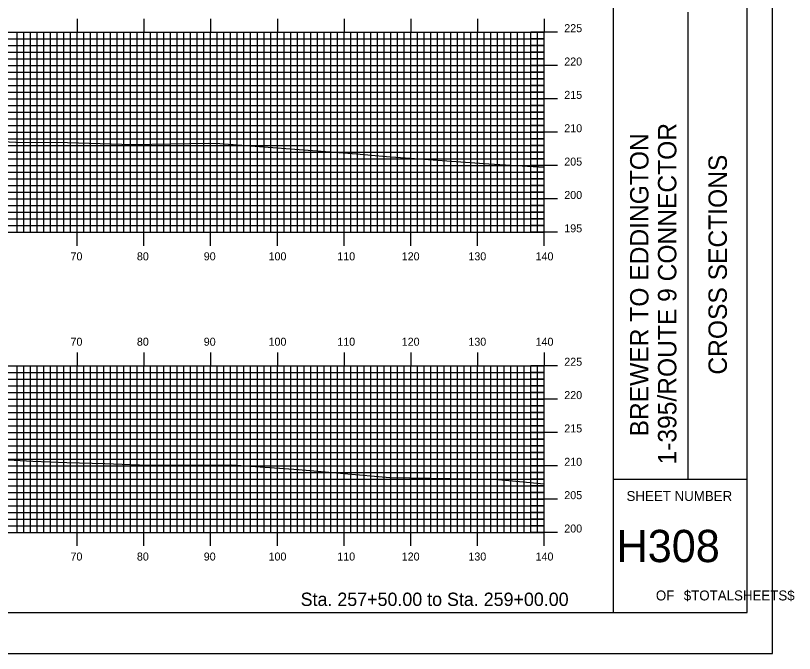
# Model space of a CAD drawing. Extents: x 1805471 to 1805814, y 442591 to 442811.
# Drawn here: x 1805697.5 to 1805814.2, y 442590.5 to 442686.2 of the extents above; entities that cross this region are included whole.
import ezdxf

# ---------------------------------------------------------------- set-up
doc = ezdxf.new("R2010")
doc.units = 0
for name, color, linetype in [('BORDER', 7, 'Continuous'), ('H_V ANNOTATION', 7, 'Continuous'), ('MAJOR', 7, 'Continuous'), ('MINOR', 7, 'Continuous'), ('PLOT BOUNDARY', 7, 'Continuous'), ('S_Roadway_Centerline', 7, 'Continuous')]:
    doc.layers.add(name, color=color, linetype=linetype)

msp = doc.modelspace()

# ---------------------------------------------------------------- linework, layer by layer
at = {"layer": 'BORDER'}
for p, q in [((1805787.11, 442596.67), (1805787.11, 442806.67)), ((1805798.29, 442616.67), (1805798.29, 442686.67)), ((1805787.11, 442616.67), (1805807.11, 442616.67))]:
    msp.add_line(p, q, dxfattribs=at)
msp.add_lwpolyline([(1805487.11, 442596.67), (1805807.11, 442596.67), (1805807.11, 442806.67), (1805487.11, 442806.67)], close=True, dxfattribs=at)
at = {"layer": 'MAJOR'}
for p, q in [((1805706.71, 442685.67), (1805706.71, 442683.67)), ((1805716.71, 442685.67), (1805716.71, 442683.67)), ((1805726.71, 442685.67), (1805726.71, 442683.67)), ((1805736.71, 442685.67), (1805736.71, 442683.67)), ((1805746.71, 442685.67), (1805746.71, 442683.67)), ((1805756.71, 442685.67), (1805756.71, 442683.67)), ((1805766.71, 442685.67), (1805766.71, 442683.67)), ((1805776.71, 442685.67), (1805776.71, 442683.67)), ((1805496.71, 442683.67), (1805776.71, 442683.67)), ((1805496.71, 442683.67), (1805776.71, 442683.67)), ((1805706.71, 442653.67), (1805706.71, 442683.67)), ((1805716.71, 442653.67), (1805716.71, 442683.67)), ((1805726.71, 442653.67), (1805726.71, 442683.67)), ((1805736.71, 442653.67), (1805736.71, 442683.67)), ((1805746.71, 442653.67), (1805746.71, 442683.67)), ((1805756.71, 442653.67), (1805756.71, 442683.67)), ((1805766.71, 442653.67), (1805766.71, 442683.67)), ((1805778.71, 442683.67), (1805774.7, 442683.67)), ((1805776.71, 442653.67), (1805776.71, 442683.67)), ((1805776.71, 442653.67), (1805776.71, 442683.67)), ((1805496.71, 442678.67), (1805776.71, 442678.67)), ((1805778.71, 442678.67), (1805774.7, 442678.67)), ((1805496.71, 442673.67), (1805776.71, 442673.67)), ((1805778.71, 442673.67), (1805774.7, 442673.67)), ((1805496.71, 442668.67), (1805776.71, 442668.67)), ((1805778.71, 442668.67), (1805774.7, 442668.67)), ((1805496.71, 442663.67), (1805776.71, 442663.67)), ((1805778.71, 442663.67), (1805774.7, 442663.67)), ((1805496.71, 442658.67), (1805776.71, 442658.67)), ((1805778.71, 442658.67), (1805774.7, 442658.67)), ((1805496.71, 442653.67), (1805776.71, 442653.67)), ((1805496.71, 442653.67), (1805776.71, 442653.67)), ((1805706.71, 442651.66), (1805706.71, 442653.67)), ((1805716.71, 442651.66), (1805716.71, 442653.67)), ((1805726.71, 442651.66), (1805726.71, 442653.67)), ((1805736.71, 442651.66), (1805736.71, 442653.67)), ((1805746.71, 442651.66), (1805746.71, 442653.67)), ((1805756.71, 442651.66), (1805756.71, 442653.67)), ((1805766.71, 442651.66), (1805766.71, 442653.67)), ((1805778.71, 442653.67), (1805774.7, 442653.67)), ((1805776.71, 442651.66), (1805776.71, 442653.67)), ((1805706.71, 442635.67), (1805706.71, 442633.67)), ((1805716.71, 442635.67), (1805716.71, 442633.67)), ((1805726.71, 442635.67), (1805726.71, 442633.67)), ((1805736.71, 442635.67), (1805736.71, 442633.67)), ((1805746.71, 442635.67), (1805746.71, 442633.67)), ((1805756.71, 442635.67), (1805756.71, 442633.67)), ((1805766.71, 442635.67), (1805766.71, 442633.67)), ((1805776.71, 442635.67), (1805776.71, 442633.67)), ((1805496.71, 442633.67), (1805776.71, 442633.67)), ((1805496.71, 442633.67), (1805776.71, 442633.67)), ((1805706.71, 442608.67), (1805706.71, 442633.67)), ((1805716.71, 442608.67), (1805716.71, 442633.67)), ((1805726.71, 442608.67), (1805726.71, 442633.67)), ((1805736.71, 442608.67), (1805736.71, 442633.67)), ((1805746.71, 442608.67), (1805746.71, 442633.67)), ((1805756.71, 442608.67), (1805756.71, 442633.67)), ((1805766.71, 442608.67), (1805766.71, 442633.67)), ((1805778.71, 442633.67), (1805774.7, 442633.67)), ((1805776.71, 442608.67), (1805776.71, 442633.67)), ((1805776.71, 442608.67), (1805776.71, 442633.67)), ((1805496.71, 442628.67), (1805776.71, 442628.67)), ((1805778.71, 442628.67), (1805774.7, 442628.67)), ((1805496.71, 442623.67), (1805776.71, 442623.67)), ((1805778.71, 442623.67), (1805774.7, 442623.67)), ((1805496.71, 442618.67), (1805776.71, 442618.67)), ((1805778.71, 442618.67), (1805774.7, 442618.67)), ((1805496.71, 442613.67), (1805776.71, 442613.67)), ((1805778.71, 442613.67), (1805774.7, 442613.67)), ((1805496.71, 442608.67), (1805776.71, 442608.67)), ((1805496.71, 442608.67), (1805776.71, 442608.67)), ((1805706.71, 442606.66), (1805706.71, 442608.67)), ((1805716.71, 442606.66), (1805716.71, 442608.67)), ((1805726.71, 442606.66), (1805726.71, 442608.67)), ((1805736.71, 442606.66), (1805736.71, 442608.67)), ((1805746.71, 442606.66), (1805746.71, 442608.67)), ((1805756.71, 442606.66), (1805756.71, 442608.67)), ((1805766.71, 442606.66), (1805766.71, 442608.67)), ((1805778.71, 442608.67), (1805774.7, 442608.67)), ((1805776.71, 442606.66), (1805776.71, 442608.67))]:
    msp.add_line(p, q, dxfattribs=at)
at = {"layer": 'MINOR'}
for p, q in [((1805697.71, 442653.67), (1805697.71, 442683.67)), ((1805698.71, 442653.67), (1805698.71, 442683.67)), ((1805699.71, 442653.67), (1805699.71, 442683.67)), ((1805700.71, 442653.67), (1805700.71, 442683.67)), ((1805701.71, 442653.67), (1805701.71, 442683.67)), ((1805702.71, 442653.67), (1805702.71, 442683.67)), ((1805703.71, 442653.67), (1805703.71, 442683.67)), ((1805704.71, 442653.67), (1805704.71, 442683.67)), ((1805705.71, 442653.67), (1805705.71, 442683.67)), ((1805707.71, 442653.67), (1805707.71, 442683.67)), ((1805708.71, 442653.67), (1805708.71, 442683.67)), ((1805709.71, 442653.67), (1805709.71, 442683.67)), ((1805710.71, 442653.67), (1805710.71, 442683.67)), ((1805711.71, 442653.67), (1805711.71, 442683.67)), ((1805712.71, 442653.67), (1805712.71, 442683.67)), ((1805713.71, 442653.67), (1805713.71, 442683.67)), ((1805714.71, 442653.67), (1805714.71, 442683.67)), ((1805715.71, 442653.67), (1805715.71, 442683.67)), ((1805717.71, 442653.67), (1805717.71, 442683.67)), ((1805718.71, 442653.67), (1805718.71, 442683.67)), ((1805719.71, 442653.67), (1805719.71, 442683.67)), ((1805720.71, 442653.67), (1805720.71, 442683.67)), ((1805721.71, 442653.67), (1805721.71, 442683.67)), ((1805722.71, 442653.67), (1805722.71, 442683.67)), ((1805723.71, 442653.67), (1805723.71, 442683.67)), ((1805724.71, 442653.67), (1805724.71, 442683.67)), ((1805725.71, 442653.67), (1805725.71, 442683.67)), ((1805727.71, 442653.67), (1805727.71, 442683.67)), ((1805728.71, 442653.67), (1805728.71, 442683.67)), ((1805729.71, 442653.67), (1805729.71, 442683.67)), ((1805730.71, 442653.67), (1805730.71, 442683.67)), ((1805731.71, 442653.67), (1805731.71, 442683.67)), ((1805732.71, 442653.67), (1805732.71, 442683.67)), ((1805733.71, 442653.67), (1805733.71, 442683.67)), ((1805734.71, 442653.67), (1805734.71, 442683.67)), ((1805735.71, 442653.67), (1805735.71, 442683.67)), ((1805737.71, 442653.67), (1805737.71, 442683.67)), ((1805738.71, 442653.67), (1805738.71, 442683.67)), ((1805739.71, 442653.67), (1805739.71, 442683.67)), ((1805740.71, 442653.67), (1805740.71, 442683.67)), ((1805741.71, 442653.67), (1805741.71, 442683.67)), ((1805742.71, 442653.67), (1805742.71, 442683.67)), ((1805743.71, 442653.67), (1805743.71, 442683.67)), ((1805744.71, 442653.67), (1805744.71, 442683.67)), ((1805745.71, 442653.67), (1805745.71, 442683.67)), ((1805747.71, 442653.67), (1805747.71, 442683.67)), ((1805748.71, 442653.67), (1805748.71, 442683.67)), ((1805749.71, 442653.67), (1805749.71, 442683.67)), ((1805750.71, 442653.67), (1805750.71, 442683.67)), ((1805751.71, 442653.67), (1805751.71, 442683.67)), ((1805752.71, 442653.67), (1805752.71, 442683.67)), ((1805753.71, 442653.67), (1805753.71, 442683.67)), ((1805754.71, 442653.67), (1805754.71, 442683.67)), ((1805755.71, 442653.67), (1805755.71, 442683.67)), ((1805757.71, 442653.67), (1805757.71, 442683.67)), ((1805758.71, 442653.67), (1805758.71, 442683.67)), ((1805759.71, 442653.67), (1805759.71, 442683.67)), ((1805760.71, 442653.67), (1805760.71, 442683.67)), ((1805761.71, 442653.67), (1805761.71, 442683.67)), ((1805762.71, 442653.67), (1805762.71, 442683.67)), ((1805763.71, 442653.67), (1805763.71, 442683.67)), ((1805764.71, 442653.67), (1805764.71, 442683.67)), ((1805765.71, 442653.67), (1805765.71, 442683.67)), ((1805767.71, 442653.67), (1805767.71, 442683.67)), ((1805768.71, 442653.67), (1805768.71, 442683.67)), ((1805769.71, 442653.67), (1805769.71, 442683.67)), ((1805770.71, 442653.67), (1805770.71, 442683.67)), ((1805771.71, 442653.67), (1805771.71, 442683.67)), ((1805772.71, 442653.67), (1805772.71, 442683.67)), ((1805773.71, 442653.67), (1805773.71, 442683.67)), ((1805774.71, 442653.67), (1805774.71, 442683.67)), ((1805775.71, 442653.67), (1805775.71, 442683.67)), ((1805496.71, 442682.67), (1805776.71, 442682.67)), ((1805776.71, 442682.67), (1805774.7, 442682.67)), ((1805496.71, 442681.67), (1805776.71, 442681.67)), ((1805776.71, 442681.67), (1805774.7, 442681.67)), ((1805496.71, 442680.67), (1805776.71, 442680.67)), ((1805776.71, 442680.67), (1805774.7, 442680.67)), ((1805496.71, 442679.67), (1805776.71, 442679.67)), ((1805776.71, 442679.67), (1805774.7, 442679.67)), ((1805496.71, 442677.67), (1805776.71, 442677.67)), ((1805776.71, 442677.67), (1805774.7, 442677.67)), ((1805496.71, 442676.67), (1805776.71, 442676.67)), ((1805776.71, 442676.67), (1805774.7, 442676.67)), ((1805496.71, 442675.67), (1805776.71, 442675.67)), ((1805776.71, 442675.67), (1805774.7, 442675.67)), ((1805496.71, 442674.67), (1805776.71, 442674.67)), ((1805776.71, 442674.67), (1805774.7, 442674.67)), ((1805496.71, 442672.67), (1805776.71, 442672.67)), ((1805496.71, 442671.67), (1805776.71, 442671.67)), ((1805776.71, 442672.67), (1805774.7, 442672.67)), ((1805776.71, 442671.67), (1805774.7, 442671.67)), ((1805496.71, 442670.67), (1805776.71, 442670.67)), ((1805776.71, 442670.67), (1805774.7, 442670.67)), ((1805496.71, 442669.67), (1805776.71, 442669.67)), ((1805776.71, 442669.67), (1805774.7, 442669.67)), ((1805496.71, 442667.67), (1805776.71, 442667.67)), ((1805776.71, 442667.67), (1805774.7, 442667.67)), ((1805496.71, 442666.67), (1805776.71, 442666.67)), ((1805776.71, 442666.67), (1805774.7, 442666.67)), ((1805496.71, 442665.67), (1805776.71, 442665.67)), ((1805496.71, 442664.67), (1805776.71, 442664.67)), ((1805776.71, 442665.67), (1805774.7, 442665.67)), ((1805776.71, 442664.67), (1805774.7, 442664.67)), ((1805496.71, 442662.67), (1805776.71, 442662.67)), ((1805776.71, 442662.67), (1805774.7, 442662.67)), ((1805496.71, 442661.67), (1805776.71, 442661.67)), ((1805776.71, 442661.67), (1805774.7, 442661.67)), ((1805496.71, 442660.67), (1805776.71, 442660.67)), ((1805776.71, 442660.67), (1805774.7, 442660.67)), ((1805496.71, 442659.67), (1805776.71, 442659.67)), ((1805776.71, 442659.67), (1805774.7, 442659.67)), ((1805496.71, 442657.67), (1805776.71, 442657.67)), ((1805776.71, 442657.67), (1805774.7, 442657.67)), ((1805496.71, 442656.67), (1805776.71, 442656.67)), ((1805776.71, 442656.67), (1805774.7, 442656.67)), ((1805496.71, 442655.67), (1805776.71, 442655.67)), ((1805776.71, 442655.67), (1805774.7, 442655.67)), ((1805496.71, 442654.67), (1805776.71, 442654.67)), ((1805776.71, 442654.67), (1805774.7, 442654.67)), ((1805697.71, 442608.67), (1805697.71, 442633.67)), ((1805698.71, 442608.67), (1805698.71, 442633.67)), ((1805699.71, 442608.67), (1805699.71, 442633.67)), ((1805700.71, 442608.67), (1805700.71, 442633.67)), ((1805701.71, 442608.67), (1805701.71, 442633.67)), ((1805702.71, 442608.67), (1805702.71, 442633.67)), ((1805703.71, 442608.67), (1805703.71, 442633.67)), ((1805704.71, 442608.67), (1805704.71, 442633.67)), ((1805705.71, 442608.67), (1805705.71, 442633.67)), ((1805707.71, 442608.67), (1805707.71, 442633.67)), ((1805708.71, 442608.67), (1805708.71, 442633.67)), ((1805709.71, 442608.67), (1805709.71, 442633.67)), ((1805710.71, 442608.67), (1805710.71, 442633.67)), ((1805711.71, 442608.67), (1805711.71, 442633.67)), ((1805712.71, 442608.67), (1805712.71, 442633.67)), ((1805713.71, 442608.67), (1805713.71, 442633.67)), ((1805714.71, 442608.67), (1805714.71, 442633.67)), ((1805715.71, 442608.67), (1805715.71, 442633.67)), ((1805717.71, 442608.67), (1805717.71, 442633.67)), ((1805718.71, 442608.67), (1805718.71, 442633.67)), ((1805719.71, 442608.67), (1805719.71, 442633.67)), ((1805720.71, 442608.67), (1805720.71, 442633.67)), ((1805721.71, 442608.67), (1805721.71, 442633.67)), ((1805722.71, 442608.67), (1805722.71, 442633.67)), ((1805723.71, 442608.67), (1805723.71, 442633.67)), ((1805724.71, 442608.67), (1805724.71, 442633.67)), ((1805725.71, 442608.67), (1805725.71, 442633.67)), ((1805727.71, 442608.67), (1805727.71, 442633.67)), ((1805728.71, 442608.67), (1805728.71, 442633.67)), ((1805729.71, 442608.67), (1805729.71, 442633.67)), ((1805730.71, 442608.67), (1805730.71, 442633.67)), ((1805731.71, 442608.67), (1805731.71, 442633.67)), ((1805732.71, 442608.67), (1805732.71, 442633.67)), ((1805733.71, 442608.67), (1805733.71, 442633.67)), ((1805734.71, 442608.67), (1805734.71, 442633.67)), ((1805735.71, 442608.67), (1805735.71, 442633.67)), ((1805737.71, 442608.67), (1805737.71, 442633.67)), ((1805738.71, 442608.67), (1805738.71, 442633.67)), ((1805739.71, 442608.67), (1805739.71, 442633.67)), ((1805740.71, 442608.67), (1805740.71, 442633.67)), ((1805741.71, 442608.67), (1805741.71, 442633.67)), ((1805742.71, 442608.67), (1805742.71, 442633.67)), ((1805743.71, 442608.67), (1805743.71, 442633.67)), ((1805744.71, 442608.67), (1805744.71, 442633.67)), ((1805745.71, 442608.67), (1805745.71, 442633.67)), ((1805747.71, 442608.67), (1805747.71, 442633.67)), ((1805748.71, 442608.67), (1805748.71, 442633.67)), ((1805749.71, 442608.67), (1805749.71, 442633.67)), ((1805750.71, 442608.67), (1805750.71, 442633.67)), ((1805751.71, 442608.67), (1805751.71, 442633.67)), ((1805752.71, 442608.67), (1805752.71, 442633.67)), ((1805753.71, 442608.67), (1805753.71, 442633.67)), ((1805754.71, 442608.67), (1805754.71, 442633.67)), ((1805755.71, 442608.67), (1805755.71, 442633.67)), ((1805757.71, 442608.67), (1805757.71, 442633.67)), ((1805758.71, 442608.67), (1805758.71, 442633.67)), ((1805759.71, 442608.67), (1805759.71, 442633.67)), ((1805760.71, 442608.67), (1805760.71, 442633.67)), ((1805761.71, 442608.67), (1805761.71, 442633.67)), ((1805762.71, 442608.67), (1805762.71, 442633.67)), ((1805763.71, 442608.67), (1805763.71, 442633.67)), ((1805764.71, 442608.67), (1805764.71, 442633.67)), ((1805765.71, 442608.67), (1805765.71, 442633.67)), ((1805767.71, 442608.67), (1805767.71, 442633.67)), ((1805768.71, 442608.67), (1805768.71, 442633.67)), ((1805769.71, 442608.67), (1805769.71, 442633.67)), ((1805770.71, 442608.67), (1805770.71, 442633.67)), ((1805771.71, 442608.67), (1805771.71, 442633.67)), ((1805772.71, 442608.67), (1805772.71, 442633.67)), ((1805773.71, 442608.67), (1805773.71, 442633.67)), ((1805774.71, 442608.67), (1805774.71, 442633.67)), ((1805775.71, 442608.67), (1805775.71, 442633.67)), ((1805496.71, 442632.67), (1805776.71, 442632.67)), ((1805776.71, 442632.67), (1805774.7, 442632.67)), ((1805496.71, 442631.67), (1805776.71, 442631.67)), ((1805776.71, 442631.67), (1805774.7, 442631.67)), ((1805496.71, 442630.67), (1805776.71, 442630.67)), ((1805496.71, 442629.67), (1805776.71, 442629.67)), ((1805776.71, 442630.67), (1805774.7, 442630.67)), ((1805776.71, 442629.67), (1805774.7, 442629.67)), ((1805496.71, 442627.67), (1805776.71, 442627.67)), ((1805776.71, 442627.67), (1805774.7, 442627.67)), ((1805496.71, 442626.67), (1805776.71, 442626.67)), ((1805776.71, 442626.67), (1805774.7, 442626.67)), ((1805496.71, 442625.67), (1805776.71, 442625.67)), ((1805776.71, 442625.67), (1805774.7, 442625.67)), ((1805496.71, 442624.67), (1805776.71, 442624.67)), ((1805776.71, 442624.67), (1805774.7, 442624.67)), ((1805496.71, 442622.67), (1805776.71, 442622.67)), ((1805776.71, 442622.67), (1805774.7, 442622.67)), ((1805496.71, 442621.67), (1805776.71, 442621.67)), ((1805776.71, 442621.67), (1805774.7, 442621.67)), ((1805496.71, 442620.67), (1805776.71, 442620.67)), ((1805776.71, 442620.67), (1805774.7, 442620.67)), ((1805496.71, 442619.67), (1805776.71, 442619.67)), ((1805776.71, 442619.67), (1805774.7, 442619.67)), ((1805496.71, 442617.67), (1805776.71, 442617.67)), ((1805496.71, 442616.67), (1805776.71, 442616.67)), ((1805776.71, 442617.67), (1805774.7, 442617.67)), ((1805776.71, 442616.67), (1805774.7, 442616.67)), ((1805496.71, 442615.67), (1805776.71, 442615.67)), ((1805776.71, 442615.67), (1805774.7, 442615.67)), ((1805496.71, 442614.67), (1805776.71, 442614.67)), ((1805776.71, 442614.67), (1805774.7, 442614.67)), ((1805496.71, 442612.67), (1805776.71, 442612.67)), ((1805776.71, 442612.67), (1805774.7, 442612.67)), ((1805496.71, 442611.67), (1805776.71, 442611.67)), ((1805776.71, 442611.67), (1805774.7, 442611.67)), ((1805496.71, 442610.67), (1805776.71, 442610.67)), ((1805496.71, 442609.67), (1805776.71, 442609.67)), ((1805776.71, 442610.67), (1805774.7, 442610.67)), ((1805776.71, 442609.67), (1805774.7, 442609.67))]:
    msp.add_line(p, q, dxfattribs=at)
at = {"layer": 'PLOT BOUNDARY'}
msp.add_lwpolyline([(1805470.92, 442590.55), (1805810.92, 442590.55), (1805810.92, 442810.55), (1805470.92, 442810.55)], close=True, dxfattribs=at)
at = {"layer": 'S_Roadway_Centerline'}
for points in [[(1805677.43, 442668.19), (1805697.5, 442667.16), (1805705.27, 442667.13), (1805715.07, 442666.81), (1805726.35, 442667.05), (1805728.1, 442666.97), (1805748.58, 442665.44), (1805753.06, 442665.05), (1805768.38, 442663.95), (1805776.71, 442663.46)], [(1805694.37, 442619.66), (1805700.06, 442619.38), (1805705.14, 442619.15), (1805710.85, 442619), (1805717.35, 442618.75), (1805729.82, 442618.81), (1805739.89, 442618.11), (1805753.56, 442616.94), (1805768.59, 442616.68), (1805769.31, 442616.66), (1805776.71, 442615.97)]]:
    msp.add_lwpolyline(points, dxfattribs=at)

# ---------------------------------------------------------------- texts
at = {"layer": 'BORDER'}
for s, p in [('1-395/ROUTE 9 CONNECTOR', (1805796.51, 442618.87)), ('BREWER TO EDDINGTON', (1805792.33, 442623.07)), ('CROSS SECTIONS', (1805804.08, 442632.34))]:
    msp.add_text(s, height=2.7557, rotation=90, dxfattribs=at).set_placement(p)
for s, height, p in [('SHEET NUMBER', 1.4905, (1805789.04, 442613.4)), ('H308', 4.839, (1805787.55, 442604.23)), ('OF', 1.491, (1805793.44, 442598.49)), ('$TOTALSHEETS$', 1.4905, (1805797.62, 442598.49))]:
    msp.add_text(s, height=height, dxfattribs=at).set_placement(p)
at = {"layer": 'H_V ANNOTATION'}
for s, height, p in [('225', 1.2, (1805779.71, 442683.67)), ('220', 1.2, (1805779.71, 442678.67)), ('215', 1.2, (1805779.71, 442673.67)), ('210', 1.2, (1805779.71, 442668.67)), ('205', 1.2, (1805779.71, 442663.67)), ('200', 1.2, (1805779.71, 442658.67)), ('195', 1.2, (1805779.71, 442653.67)), ('70', 1.2, (1805705.71, 442649.47)), ('80', 1.2, (1805715.66, 442649.47)), ('90', 1.2, (1805725.68, 442649.47)), ('100', 1.2, (1805735.39, 442649.47)), ('110', 1.2, (1805745.69, 442649.47)), ('120', 1.2, (1805755.35, 442649.47)), ('130', 1.2, (1805765.34, 442649.47)), ('140', 1.2, (1805775.41, 442649.47)), ('70', 1.2, (1805705.71, 442636.67)), ('80', 1.2, (1805715.66, 442636.67)), ('90', 1.2, (1805725.68, 442636.67)), ('100', 1.2, (1805735.39, 442636.67)), ('110', 1.2, (1805745.69, 442636.67)), ('120', 1.2, (1805755.35, 442636.67)), ('130', 1.2, (1805765.34, 442636.67)), ('140', 1.2, (1805775.41, 442636.67)), ('225', 1.2, (1805779.71, 442633.67)), ('220', 1.2, (1805779.71, 442628.67)), ('215', 1.2, (1805779.71, 442623.67)), ('210', 1.2, (1805779.71, 442618.67)), ('205', 1.2, (1805779.71, 442613.67)), ('200', 1.2, (1805779.71, 442608.67)), ('70', 1.2, (1805705.71, 442604.47)), ('80', 1.2, (1805715.66, 442604.47)), ('90', 1.2, (1805725.68, 442604.47)), ('100', 1.2, (1805735.39, 442604.47)), ('110', 1.2, (1805745.69, 442604.47)), ('120', 1.2, (1805755.35, 442604.47)), ('130', 1.2, (1805765.34, 442604.47)), ('140', 1.2, (1805775.41, 442604.47)), ('Sta. 257+50.00 to Sta. 259+00.00', 2.0004, (1805740.2, 442597.66))]:
    msp.add_text(s, height=height, dxfattribs=at).set_placement(p)

doc.saveas('drawing.dxf')
